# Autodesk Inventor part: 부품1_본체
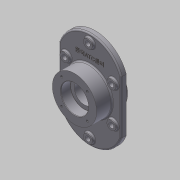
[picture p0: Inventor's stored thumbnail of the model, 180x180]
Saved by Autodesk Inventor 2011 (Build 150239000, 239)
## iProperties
Created: 2015-02
Part Number: 부품1_본체
Document SubType Name: Modeling
Designer: user
Density: 2.71 g/cm^3
Material: 알루미늄-6061
Mass: 1626.28 g
Surface Area: 923.626 cm^2
Volume: 600.103 cm^3
Author: user
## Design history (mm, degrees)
sketch "스케치1"
  geometry: L1 (70, 60)-(70, -60); L2 (-70, 60)-(-70, -60); A1 r 74 centre (0, 36) between (70, 60) and (-70, 60); A2 r 74 centre (0, -36) between (-70, -60) and (70, -60)
  constraints: 4 end point, 4 point on circle, 2 centre point, 1 parallel
extrude "돌출1" new body sketch "스케치1" distance "d9" = 12; taper "d10" = 0 deg
sketch "스케치3"
  geometry: C1 r 50 at (0, 0); 1 further point
  constraints: 1 centre point, 1 coincident
  dimensions: "d11" = 100 diameter of C1
extrude "돌출2" join sketch "스케치3" distance "d12" = 23; taper "d13" = 0 deg
sketch "스케치4"
  geometry: C1 r 50 at (0, 0); 1 further point
  constraints: 1 centre point, 1 coincident
  dimensions: "d14" = 100 diameter of C1
extrude "돌출3" join sketch "스케치4" distance "d15" = 35; taper "d16" = 0 deg
hole "Hole1" diameter "d19" = 62; stored, may be unused: countersink angle "d23" = 90 deg, drill point angle "d25" = 0 deg; dims "d17" = 10, "d18" = 10, "d20" = 6, "d21" = 4, "d22" = 2, "d24" = 22
hole "Hole2" diameter "d28" = 62; stored, may be unused: countersink angle "d32" = 90 deg, drill point angle "d34" = 0 deg; dims "d26" = 10, "d27" = 10, "d29" = 6, "d30" = 4, "d31" = 2, "d33" = 22
hole "Hole3" diameter "d37" = 45; stored, may be unused: countersink angle "d41" = 90 deg, drill point angle "d43" = 118 deg; dims "d35" = 10, "d36" = 10, "d38" = 6, "d39" = 4, "d40" = 2, "d42" = 22
sketch "스케치5"
  geometry: L1 (0, 0)-(70.711, 0); 1 further point
  constraints: 2 end point, 1 horizontal
hole "Hole4" sketch "스케치5" at (28.991, 28.991) diameter "d46" = 4.917; stored, may be unused: countersink angle "d50" = 90 deg, drill point angle "d52" = 118 deg; dims "d47" = 10, "d48" = 4, "d49" = 2, "d51" = 13
node "작업 평면1"
sketch "스케치6"
  geometry: L1 (-70, -60)-(-70, 60) reference; L2 (70, 60)-(70, -60) reference; L3 (53, 56.976)-(53, -56.976); L4 (-53, -56.976)-(-53, 56.976); C1 r 10 at (0, 93); A1 r 74 centre (0, 36) between (70, 60) and (-70, 60) reference; A2 r 74 centre (0, -36) between (-70, -60) and (70, -60) reference; A3 r 57 centre (0, 36) between (53, 56.976) and (-53, 56.976); A4 r 57 centre (0, -36) between (-53, -56.976) and (53, -56.976)
  constraints: 5 point on circle, 4 end point, 3 centre point, 3 other
  dimensions: "d56" = 17 distance between parallel lines of L2 L3; "d57" = 20 diameter of C1
extrude "돌출4" join sketch "스케치6" distance "d58" = 5; taper "d59" = 0 deg
sketch "스케치8"
  geometry: C1 r 10 at (0, -93); C2 r 10 at (-53, 40); C3 r 10 at (-50, -40); C4 r 10 at (53, 40); C5 r 10 at (53, -40)
  constraints: 5 centre point
  dimensions: "d62" = 20 diameter of C1; "d65" = 20 diameter of C2; "d66" = 20 diameter of C3; "d67" = 20 diameter of C4
extrude "돌출5" join sketch "스케치8" distance "d69" = 5; taper "d70" = 0 deg
sketch "스케치9"
  geometry: C1 r 10 at (53, 40) reference; C2 r 10 at (-50, -40) reference; C3 r 10 at (0, -93) reference; C4 r 10 at (53, -40) reference; C5 r 10 at (-53, 40) reference; C6 r 10 at (0, 93) reference; 6 further points
  constraints: 6 coincident
hole "Hole5" sketch "스케치9" at (0, 93), (53, 40), (-53, 40), (-50, -40), (0, -93), (53, -40) diameter "d71" = 11; stored, may be unused: countersink angle "d75" = 90 deg, drill point angle "d77" = 0 deg; dims "d72" = 6, "d73" = 4, "d74" = 2, "d76" = 30
sketch "스케치10"
  geometry: L1 (-70, -60)-(-70, 60) reference; L2 (70, 60)-(70, -60) reference; C1 r 10 at (53, 40) reference; C2 r 10 at (-50, -40) reference; C3 r 10 at (0, -93) reference; C4 r 10 at (53, -40) reference; C5 r 10 at (-53, 40) reference; C6 r 10 at (0, 93) reference; C7 r 50 at (0, 0) reference; A1 r 74 centre (0, 36) between (70, 60) and (-70, 60) reference; A2 r 74 centre (0, -36) between (-70, -60) and (70, -60) reference
hole "Hole6" diameter "d80" = 11; stored, may be unused: countersink angle "d84" = 90 deg, drill point angle "d86" = 118 deg; dims "d78" = 10, "d79" = 10, "d81" = 6, "d82" = 4, "d83" = 2, "d85" = 30
sketch "스케치11"
  geometry: C1 r 10 at (53, 40) reference; C2 r 10 at (-50, -40) reference; C3 r 10 at (0, -93) reference; C4 r 10 at (53, -40) reference; C5 r 10 at (-53, 40) reference; C6 r 5.5 at (-53, 40); C7 r 5.5 at (53, 40); C8 r 5.5 at (53, -40); C9 r 5.5 at (0, -93); C10 r 5.5 at (-50, -40)
  constraints: 5 centre point, 5 coincident
  dimensions: "d87" = 11 diameter of C6; "d88" = 11 diameter of C7; "d89" = 11 diameter of C8; "d90" = 11 diameter of C9; "d91" = 11 diameter of C10
extrude "돌출6" cut sketch "스케치11" distance "d92" = 20; taper "d93" = 0 deg
fillet "모깎기1" dims "d94" = 0.3
fillet "모깎기2" dims "d95" = 3
fillet "모깎기3" dims "d96" = 3
sketch "스케치12"
  geometry: L1 (-18.756, 69.803)-(18.756, 69.803); L2 (18.756, 69.803)-(18.756, 60.197); L3 (18.756, 60.197)-(-18.756, 60.197); L4 (-18.756, 60.197)-(-18.756, 69.803); L5 (0, 0)-(0, 65); A1 r 53 centre (0, 0) between (-37.195, -37.756) and (-45, -28) reference; 2 further points
  constraints: 2 end point, 2 midpoint, 1 horizontal alignment, 1 perpendicular, 1 vertical, 1 vertical alignment, 2 other
  dimensions: "d97" = 65 distance of L5.start L5.end
feature "엠보싱1" sketch "스케치12" dims "d35" = 10, "d98" = 1, "d99" = 0
fillet "모깎기4" dims "d100" = 3
chamfer "모따기1" distance "d101" = 1; stored, may be unused: second distance "d102" = 2, angle "d103" = 45 deg
node "솔리드1"
pattern_circular "원형 패턴1" dims angle "d54" = 360 deg
mirror "대칭1"
